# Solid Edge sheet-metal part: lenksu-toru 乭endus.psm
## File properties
Title: lenksu-toru ühendus
Author: Stella-Marii
Template: Iso Metric Sheet Metal.psm
Last saved by: Stella-Marii
Revision: 8
Application: Solid Edge
Document Number: 26
Density: 1024,000 kg/m^3
Accuracy: 0,990
Material Thickness: 1,00 mm
Bend Radius: 1,00 mm
Relief Width: 1,00 mm
Relief Length: 0,00 mm
Neutral Factor: 0,330
Minimum Arc Length: 0,10 mm
Deviational Tolerance: 0,10 mm
Username: Stella-Marii
Material: ABS Plastic, high impact
Face Style: Red
Fill Style: ANSI34(Plastic)
Virtual Style: Red (Shiny)
Grouping: Non-metals\Plastics
LibraryName: Materials
Coef. of Thermal Exp: 9e-05
Thermal Conductivity: 0.2
Specific Heat: 0.0
Modulus of Elasticity: 1378951400.0
Poisson's Ratio: 0.4
Yield Stress: 31026406.5
Ultimate Stress: 0.0
Elongation: 0.0
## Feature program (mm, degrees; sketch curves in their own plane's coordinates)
base contour flange "ContourFlange_1"
sheet metal cutout "SheetMetalCutout_2"
sheet metal cutout "SheetMetalCutout_4"
sheet metal cutout "SheetMetalCutout_5"
sheet metal cutout "SheetMetalCutout_6"
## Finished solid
Body 1: solid body, 26 faces, 61 edges, 36 vertices.
  Faces by surface: plane 12, spline 8, cylinder 6
  Edges by curve: line 33, circle 10, ellipse 10, curve on surface 6, intersection 2
Bounding box of the edges (mm; curved faces can reach further): 47.000 x 70.500 x 48.801, from (-23.5, -47, 0) to (23.5, 23.5, 48.8009).
Cylindrical faces by radius (mm): R12.5 x2, R22.5 x2, R23.5 x2
Planar faces by outward normal: +x 2, +z 2, -x 2, -y 1, -z 2, oblique 3
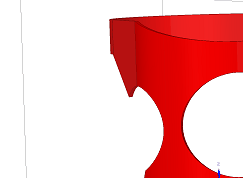
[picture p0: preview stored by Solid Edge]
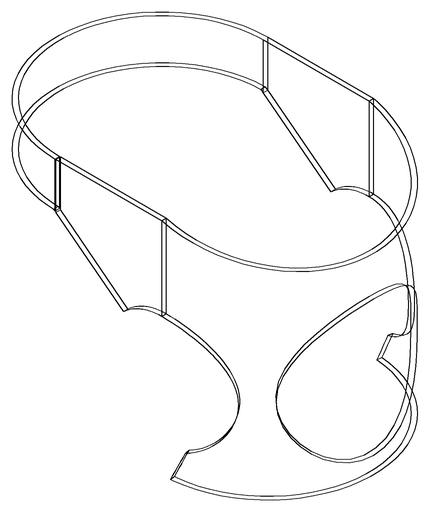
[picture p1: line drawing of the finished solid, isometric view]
